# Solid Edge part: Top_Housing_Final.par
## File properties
Author: Chalangana Oshan
Template: iso metric part.par
Last saved by: Chalangana Oshan
Revision: 34
Application: Solid Edge
Density: 7250.000 kg/m^3
Accuracy: 0.990
Username: Nimesh.N
Material: Iron:0.6010 , EN-GJL-100
Face Style: Gray
Fill Style: ANSI31(Iron)
Virtual Style: ANSI31(Iron)
Grouping: Iron\Gray Cast Iron
LibraryName: Materials-DIN
Coef. of Thermal Exp: 1.05e-05
Thermal Conductivity: 58.0
Specific Heat: 460.0
Modulus of Elasticity: 185000000000.0
Poisson's Ratio: 0.26
Yield Stress: 100594000.0
Ultimate Stress: 150826000.0
Elongation: 0.0
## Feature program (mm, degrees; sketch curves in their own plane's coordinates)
sketch for "unnamed Protrusion 1" plane through (0, 0, 0) normal (0, -1, 0) x-axis (1, 0, 0)
  line (372.619, 154.6126) -> (96.0317, 257.6876)
  arc centre (0, 0) radius 275 from (96.0317, 257.6876) to (8.7302, -274.8614) ccw
  line (8.7302, -274.8614) -> (333.535, -264.5449)
  line (333.535, -264.5449) -> (451.0326, -93.3816)
  arc centre (315, 0) radius 165 from (451.0326, -93.3816) to (372.619, 154.6126) ccw
extrude "unnamed Protrusion 1" add finite 1140 along -normal
sketch for "unnamed Cutout 1" plane through (0, 0, 0) normal (0, -1, 0) x-axis (1, 0, 0)
  line (89.0476, 238.9467) -> (365.6349, 135.8716)
  line (434.5438, -82.0626) -> (322.7778, -244.8765)
  line (8.0952, -254.8715) -> (322.7778, -244.8765)
extrude "unnamed Cutout 1" cut through along -normal
sketch for "ExtrudedProtrusion_2" plane through (0, 0, 0) normal (0, -1, 0) x-axis (1, 0, 0)
  arc centre (315, 0) radius 265 from (201.4286, 239.4296) to (323.4127, -264.8664) cw
  line (323.4127, -264.8664) -> (-3.8692, -275.2616)
  line (-3.8692, -275.2616) -> (-115.4432, -59.7734)
  arc centre (0, 0) radius 130 from (-115.4432, -59.7734) to (-55.7143, 117.456) cw
  line (-55.7143, 117.456) -> (201.4286, 239.4296)
extrude "ExtrudedProtrusion_2" add finite 260 along +normal
sketch for "unnamed Cutout 2" plane through (0, 0, 0) normal (0, -1, 0) x-axis (1, 0, 0)
  line (8.0952, -254.8715) -> (322.7778, -244.8765)
  line (-97.6827, -50.5775) -> (8.0952, -254.8715)
  line (-47.1429, 99.3859) -> (210, 221.3594)
extrude "unnamed Cutout 2" cut through along +normal
sketch for "ExtrudedProtrusion_5" plane through (225, -260, -5.1308) normal (0, -1, 0) x-axis (0.999496, 0, 0.031746)
  arc centre (90.1175, 2.2711) radius 265 from (90.1175, -262.7289) to (-15.7957, 245.1854) ccw
  line (-15.7957, 245.1854) -> (-276.6812, 131.4366)
  arc centre (-224.7237, 12.2711) radius 130 from (-342.0063, -43.8074) to (-276.6812, 131.4366) cw
  line (-342.0063, -43.8074) -> (-237.3294, -262.7289)
  line (-237.3294, -262.7289) -> (90.1175, -262.7289)
extrude "ExtrudedProtrusion_5" add finite 20 symmetric
sketch for "ExtrudedCutout_3" plane through (-49.194, 0, 0.0147) normal (0, -1, 0) x-axis (0.937046, 0, -0.349206)
  arc centre (46.1022, 17.0164) radius 275.1487 from (46.1022, 292.1651) to (138.5997, -242.1188) ccw
  line (138.5997, -242.1188) -> (441.6478, -118.0891)
  arc centre (341.2716, 127.1651) radius 265 from (441.6478, -118.0891) to (151.2397, 311.8618) ccw
  line (151.2397, 311.8618) -> (132.096, 292.1651)
  line (132.096, 292.1651) -> (46.1022, 292.1651)
extrude "ExtrudedCutout_3" add finite 20 symmetric
sketch for "ExtrudedProtrusion_8" plane through (102.5, 1140, 0) normal (0, 1, 0) x-axis (-0.999496, 0, -0.031746)
  arc centre (102.4483, 3.254) radius 275 from (102.4483, -271.746) to (-1.7156, 257.7631) ccw
  line (-1.7156, 257.7631) -> (-274.8912, 145.9594)
  arc centre (-212.3929, -6.746) radius 165 from (-345.3924, -104.3991) to (-274.8912, 145.9594) cw
  line (-345.3924, -104.3991) -> (-222.5203, -271.746)
  line (-222.5203, -271.746) -> (102.4483, -271.746)
extrude "ExtrudedProtrusion_8" add finite 20 symmetric
sketch for "ExtrudedProtrusion_9" plane through (225, -260, -5.1308) normal (0, -1, 0) x-axis (0.999496, 0, 0.031746)
  circle centre (-224.7237, 12.2711) radius 80
extrude "ExtrudedProtrusion_9" add finite 63 symmetric  Profile_Plane1_Distance = 10 mm
sketch for "ExtrudedCutout_4" plane through (225, -260, -5.1308) normal (0, -1, 0) x-axis (0.999496, 0, 0.031746)
  circle centre (-224.7237, 12.2711) radius 60
extrude "ExtrudedCutout_4" cut finite 23 symmetric
sketch for "ExtrudedProtrusion_10" plane through (225, -260, -5.1308) normal (0, -1, 0) x-axis (0.999496, 0, 0.031746)
  circle centre (90.1175, 2.2711) radius 80
extrude "ExtrudedProtrusion_10" add finite 63 symmetric
sketch for "ExtrudedCutout_5" plane through (225, -260, -5.1308) normal (0, -1, 0) x-axis (0.999496, 0, 0.031746)
  circle centre (90.1175, 2.2711) radius 60
extrude "ExtrudedCutout_5" cut finite 23 symmetric
sketch for "ExtrudedProtrusion_11" plane through (-49.2944, 0, -0.1261) normal (0, -1, 0) x-axis (0.903508, 0, 0.428571)
  circle centre (44.5919, -21.0122) radius 65
extrude "ExtrudedProtrusion_11" add finite 58 symmetric  Profile_Plane1_Distance = 10 mm
sketch for "ExtrudedCutout_6" plane through (-49.2944, 0, -0.1261) normal (0, -1, 0) x-axis (0.903508, 0, 0.428571)
  circle centre (44.5919, -21.0122) radius 45
extrude "ExtrudedCutout_6" cut finite 18 symmetric  Profile_Plane1_Distance = 10 mm
sketch for "ExtrudedProtrusion_12" plane through (-49.2944, 0, -0.1261) normal (0, -1, 0) x-axis (0.903508, 0, 0.428571)
  circle centre (329.1969, -156.0122) radius 90
extrude "ExtrudedProtrusion_12" add finite 88 symmetric
sketch for "ExtrudedCutout_7" plane through (-49.2944, 0, -0.1261) normal (0, -1, 0) x-axis (0.903508, 0, 0.428571)
  circle centre (329.1969, -156.0122) radius 70
extrude "ExtrudedCutout_7" cut finite 48 symmetric  Profile_Plane1_Distance = 10 mm
sketch for "ExtrudedCutout_8" plane through (102.5, 1140, 0) normal (0, 1, 0) x-axis (-0.565949, 0, -0.82444)
  circle centre (58.0098, 84.5051) radius 70
extrude "ExtrudedCutout_8" add finite 67 symmetric  Profile_Plane1_Distance = 10 mm
sketch for "ExtrudedCutout_9" plane through (102.5, 1140, 0) normal (0, 1, 0) x-axis (-0.565949, 0, -0.82444)
  circle centre (58.0098, 84.5051) radius 50
extrude "ExtrudedCutout_9" cut finite 27 symmetric
sketch for "ExtrudedProtrusion_14" plane through (102.5, 1140, 0) normal (0, 1, 0) x-axis (-0.999496, 0, -0.031746)
  circle centre (-212.3929, -6.746) radius 80
extrude "ExtrudedProtrusion_14" add finite 63 symmetric  Profile_Plane1_Distance = 10 mm
sketch for "ExtrudedCutout_10" plane through (102.5, 1140, 0) normal (0, 1, 0) x-axis (-0.999496, 0, -0.031746)
  circle centre (-212.3929, -6.746) radius 70
extrude "ExtrudedCutout_10" cut finite 33 symmetric
fillet "Round_2" radius 5
sketch for "unnamed Cutout 3" plane through (525.2542, 691.9405, 0) normal (0, 0, -1) x-axis (0, 1, 0)
extrude "unnamed Cutout 3" cut through along +normal
sketch for "unnamed Cutout 4" plane through (0, 1126.5, 25) normal (0, 1, 0) x-axis (1, 0, 0)
  circle centre (0, 25) radius 32.5
extrude "unnamed Cutout 4" cut to key point along -normal
sketch for "ExtrudedCutout_17" plane through (0, 0, 250) normal (0, 0, 1) x-axis (1, 0, 0)
extrude "ExtrudedCutout_17" cut finite 105 along +normal
sketch for "unnamed Cutout 5" plane through (0.9956, 570, 250) normal (0, 0, 1) x-axis (0, -1, 0)
extrude "unnamed Cutout 5" cut through along -normal
sketch for "unnamed Protrusion 2" #1 plane through (0.9956, 570, 250) normal (0, 0, 1) x-axis (0, 1, 0)
sketch for "unnamed Protrusion 2" #2 plane through (0.9956, 570, 250) normal (0, 0, 1) x-axis (0, 1, 0)
  line (-580, 115.6648) -> (580, 115.6648)
  line (-560, 95.6648) -> (560, 95.6648)
extrude "unnamed Protrusion 2" add finite 42.87 along +normal
sketch for "unnamed Cutout 6" #1 plane through (102.5, 1150, 146.435) normal (0, 1, 0) x-axis (-1, 0, 0)
sketch for "unnamed Cutout 6" #2 plane through (102.5, 1150, 146.435) normal (0, 1, 0) x-axis (-1, 0, 0)
extrude "unnamed Cutout 6" cut through along -normal
sketch for "unnamed Protrusion 3" #1 plane through (102.5, 1150, 146.435) normal (0, 1, 0) x-axis (-1, 0, 0)
sketch for "unnamed Protrusion 3" #2 plane through (102.5, 1150, 146.435) normal (0, 1, 0) x-axis (-1, 0, 0)
extrude "unnamed Protrusion 3" add finite 20 along +normal
sketch for "unnamed Protrusion 4" #1 plane through (-49.2943, -10, 146.435) normal (0, -1, 0) x-axis (1, 0, 0)
sketch for "unnamed Protrusion 4" #2 plane through (-49.2943, -10, 146.435) normal (0, -1, 0) x-axis (1, 0, 0)
extrude "unnamed Protrusion 4" add finite 20 along +normal
sketch for "ExtrudedProtrusion_22" plane through (-325.1992, 570, 271.435) normal (-1, 0, 0) x-axis (0, -1, 0)
  line (-580, -271.435) -> (-580, -261.435)
  line (580, -261.435) -> (-580, -261.435)
  line (580, -271.435) -> (580, -261.435)
  line (580, -271.435) -> (-580, -271.435)
extrude "ExtrudedProtrusion_22" add through along -normal  Profile_Plane1_Distance = 210.53 mm
sketch for "ExtrudedProtrusion_23" plane through (530.0004, 570, 271.435) normal (1, 0, 0) x-axis (0, 1, 0)
  line (580, -271.435) -> (580, -261.435)
  line (580, -261.435) -> (-560, -261.435)
  line (-560, -261.435) -> (-560, -271.435)
  line (-560, -271.435) -> (580, -271.435)
extrude "ExtrudedProtrusion_23" add through along -normal  Profile_Plane1_Distance = 413.34 mm
sketch for "ExtrudedProtrusion_24" plane through (630.0004, 580, 5) normal (1, 0, 0) x-axis (0, 1, 0)
  line (-850, -5) -> (-850, 5)
  line (-850, 5) -> (-570, 5)
  line (-570, 5) -> (-570, -5)
  line (-570, -5) -> (-850, -5)
  dimension (linear) = 570
extrude "ExtrudedProtrusion_24" add through along -normal  Profile_Plane1_Distance = 100 mm
sketch for "ExtrudedProtrusion_25" plane through (-179.9992, 570, 5) normal (-1, 0, 0) x-axis (0, -1, 0)
  line (580, 5) -> (580, -5)
  line (580, -5) -> (840, -5)
  line (840, -5) -> (840, 5)
  line (840, 5) -> (580, 5)
  dimension (linear) = 580
extrude "ExtrudedProtrusion_25" add through along -normal  Profile_Plane1_Distance = 145.2 mm
fillet "Round_4" radius 5
fillet "Round_5" radius 10
sketch for "ExtrudedProtrusion_26" plane through (116.6604, 570, 266.0991) normal (1, 0, 0) x-axis (0, 1, 0)
extrude "ExtrudedProtrusion_26" add finite 30 along +normal
fillet "Round_6" radius 20
sketch for "unnamed Cutout 7" plane through (15.9956, 570, 292.87) normal (0, 0, 1) x-axis (0, 1, 0)
extrude "unnamed Cutout 7" cut through along -normal
pattern "unnamed Pattern 1" of "unnamed Cutout 7"
pattern "unnamed Pattern 2"
sketch for "ExtrudedProtrusion_27" plane through (-114.6692, 569.7259, 265.6391) normal (-1, 0, 0) x-axis (0, -1, 0)
  line (-580, 26.7709) -> (580, 26.7709)
  line (580, 26.7709) -> (580, 16.7709)
  line (580, 16.7709) -> (-580, 16.7709)
  line (-580, 16.7709) -> (-580, 26.7709)
extrude "ExtrudedProtrusion_27" add finite 30 along +normal
fillet "Round_7" radius 20
sketch for "unnamed Cutout 8" plane through (0.9956, 570, 292.87) normal (0, 0, 1) x-axis (0, -1, 0)
extrude "unnamed Cutout 8" cut through along -normal
pattern "unnamed Pattern 3" of "unnamed Cutout 8"
pattern "unnamed Pattern 4"
sketch for "ExtrudedProtrusion_28" plane through (225.0006, -317, 127.5) normal (0, -1, 0) x-axis (1, 0, 0)
extrude "ExtrudedProtrusion_28" add through along -normal  Profile_Plane1_Distance = 47 mm
sketch for "ExtrudedProtrusion_29" plane through (102.4006, 1200, 146.435) normal (0, 1, 0) x-axis (-1, 0, 0)
extrude "ExtrudedProtrusion_29" add through along -normal  Profile_Plane1_Distance = 50 mm
sketch for "unnamed Cutout 9" plane through (0, -228.5, 37.5) normal (0, 1, 0) x-axis (1, 0, 0)
extrude "unnamed Cutout 9" cut through along -normal
sketch for "unnamed Cutout 10" plane through (0, 1153.5, 25) normal (0, -1, 0) x-axis (-1, 0, 0)
extrude "unnamed Cutout 10" cut through along -normal
fillet "Round_8" radius 40
sketch for "unnamed Cutout 11" plane through (0, -291.5, 42.5) normal (0, -1, 0) x-axis (1, 0, 0)
extrude "unnamed Cutout 11" cut through along +normal
sketch for "unnamed Cutout 12" plane through (0, 1173.5, 37.5) normal (0, 1, 0) x-axis (-1, 0, 0)
extrude "unnamed Cutout 12" cut through along +normal
fillet "Round_12" radius 25
fillet "Round_13" radius 3
Other named dimensions: "ExtrudedSurface_1": FiniteDepth = 1383.881 mm
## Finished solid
Body 1: sheet body, 1 face, 4 edges, 4 vertices.
  Faces by surface: plane 1
  Edges by curve: line 4
Body 2: solid body, 180 faces, 489 edges, 303 vertices.
  Faces by surface: cylinder 81, plane 66, torus 29, blend 4
  Edges by curve: line 253, circle 203, intersection 30, ellipse 3
Bounding box of the edges (mm; curved faces can reach further): 1060.707 x 1700.881 x 292.870, from (-325.1992, -317, 0) to (735.5083, 1383.881, 292.87).
Cylindrical faces by radius (mm): R3 x14, R7.5 x14, R10 x4, R20 x4, R27.5 x4, R32.5 x3, R40 x9, R45 x1, R50 x1, R60 x2, R65 x1, R70 x3, R80 x8, R87.5 x2, R90 x2, R110 x1, R130 x1, R145 x1, R165 x1, R245 x1, R255 x1, R265 x1, R275 x1, R275.1487 x1
Toroidal faces (ring radius, tube radius in mm): R37 r3 x6, R43 r3 x2, R60 r5 x1, R65 r5 x1, R75 r5 x6, R85 r5 x2, R105 r25 x2, R112.5 r25 x2, R120 r10 x1, R140 r10 x1, R155 r10 x1, R255 r10 x2, R265 r10 x1, R265.1487 r10 x1
Planar faces by outward normal: +x 5, +y 22, +z 5, -x 5, -y 21, -z 4, oblique 4
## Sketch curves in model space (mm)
line (315, 0, 0) -> (735.5083, 0, 0)
line (8.0952, 0, -254.8715) -> (322.7778, 0, -244.8765)
line (8.0952, 0, -254.8715) -> (322.7778, 0, -244.8765)
circle centre (0, 0, 0) radius 90
circle centre (0, 0, 0) radius 235
circle centre (315, 0, 0) radius 125
line (323.4127, 0, -264.8664) -> (-3.8692, 0, -275.2616)
line (-3.8692, 0, -275.2616) -> (-115.4432, 0, -59.7734)
arc centre (0, 0, 0) radius 130 from (-115.4432, 0, -59.7734) through (-121.9033, 0, 45.1617) to (-55.7143, 0, 117.456)
line (-55.7143, 0, 117.456) -> (201.4286, 0, 239.4296)
arc centre (315, 0, 0) radius 265 from (201.4286, 0, 239.4296) through (572.5718, 0, 62.304) to (323.4127, 0, -264.8664)
line (333.535, 0, -264.5449) -> (451.0326, 0, -93.3816)
arc centre (315, 0, 0) radius 165 from (451.0326, 0, -93.3816) through (470.799, 0, 54.3293) to (372.619, 0, 154.6126)
line (372.619, 0, 154.6126) -> (96.0317, 0, 257.6876)
arc centre (0, 0, 0) radius 275 from (96.0317, 0, 257.6876) through (-272.587, 0, 36.3502) to (8.7302, 0, -274.8614)
line (8.7302, 0, -274.8614) -> (333.535, 0, -264.5449)
arc centre (315, 0, 0) radius 245 from (210, 0, 221.3594) through (553.1324, 0, 57.6018) to (322.7778, 0, -244.8765)
line (-97.6827, 0, -50.5775) -> (8.0952, 0, -254.8715)
arc centre (0, 0, 0) radius 110 from (-97.6827, 0, -50.5775) through (-103.149, 0, 38.2137) to (-47.1429, 0, 99.3859)
line (-47.1429, 0, 99.3859) -> (210, 0, 221.3594)
line (434.5438, 0, -82.0626) -> (322.7778, 0, -244.8765)
arc centre (315, 0, 0) radius 145 from (365.6349, 0, 135.8716) through (454.4742, 0, 39.6476) to (434.5438, 0, -82.0626)
arc centre (0, 0, 0) radius 255 from (8.0952, 0, -254.8715) through (-250.2947, 0, 48.7604) to (89.0476, 0, 238.9467)
line (89.0476, 0, 238.9467) -> (365.6349, 0, 135.8716)
line (0, 0, 0) -> (315, 0, 0)
circle centre (315, 0, 0) radius 225
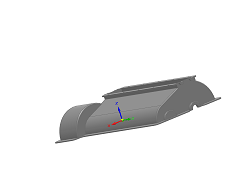
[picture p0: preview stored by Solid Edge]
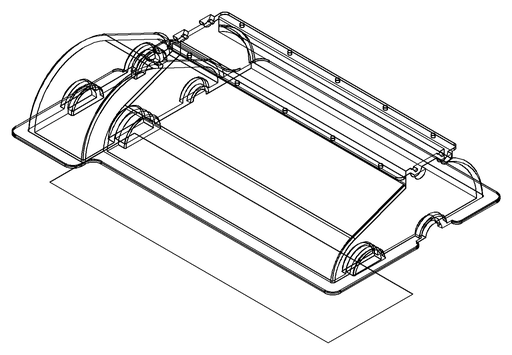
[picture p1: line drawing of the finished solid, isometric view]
